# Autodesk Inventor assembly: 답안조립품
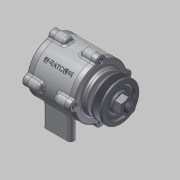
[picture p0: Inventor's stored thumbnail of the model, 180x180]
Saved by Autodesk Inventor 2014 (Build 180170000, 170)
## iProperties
Created: 2015-03
Part Number: 답안조립품
Document SubType Name: Assembly
Designer: MYHOME
Author: MYHOME
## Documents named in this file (11)
- C:\Documents and Settings\MYHOME\바탕 화면\450306v1008\답안조립품.iam
- C:\Documents and Settings\MYHOME\바탕 화면\450306v1008\본체.ipt
- C:\Documents and Settings\MYHOME\바탕 화면\450306v1008\커버2.ipt
- C:\Documents and Settings\MYHOME\바탕 화면\450306v1008\M 4 x 12.ipt
- C:\Documents and Settings\MYHOME\바탕 화면\450306v1008\커버.ipt
- C:\Documents and Settings\MYHOME\바탕 화면\450306v1008\오일실.ipt
- C:\Documents and Settings\MYHOME\바탕 화면\450306v1008\베어링 6204.ipt
- C:\Documents and Settings\MYHOME\바탕 화면\450306v1008\축.ipt
- C:\Documents and Settings\MYHOME\바탕 화면\450306v1008\키(4 x 4 x 12).ipt
- C:\Documents and Settings\MYHOME\바탕 화면\450306v1008\V벨트풀리.ipt
- C:\Documents and Settings\MYHOME\바탕 화면\450306v1008\너트 M12x1.25.ipt
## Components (14 placed, 6 different names)
1. KS B 2804 D D - 20 32 8:1
2. KS B 2023 6204 - 20 x 47 x 14:1
3. KS B 2023 6204 - 20 x 47 x 14:2
4. KS B 1311 (I) 4 x 4 x 12:1
5. 그루브 풀리1:1
6. KS B 1012 클래스 1 일반 - 미터 M12x1.25:1
7. KS B 1003 - 미터 M 4 x 12:1
8. KS B 1003 - 미터 M 4 x 12:2
9. KS B 1003 - 미터 M 4 x 12:3
10. KS B 1003 - 미터 M 4 x 12:4
11. KS B 1003 - 미터 M 4 x 12:5
12. KS B 1003 - 미터 M 4 x 12:6
13. KS B 1003 - 미터 M 4 x 12:7
14. KS B 1003 - 미터 M 4 x 12:8
